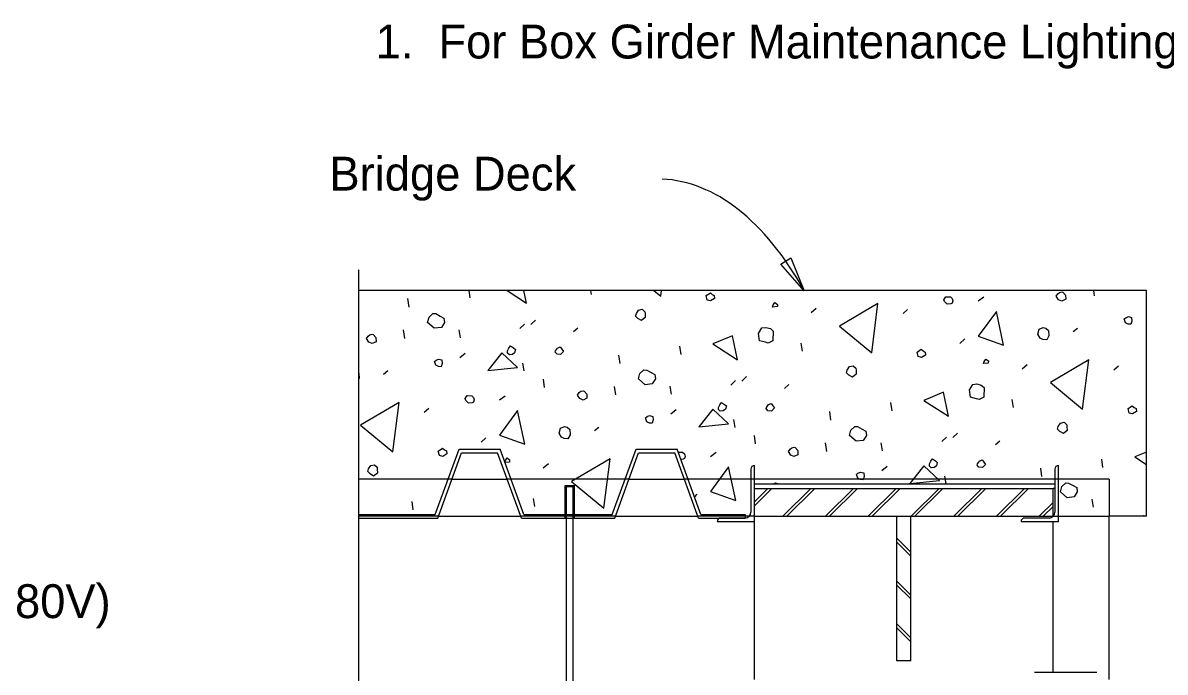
# Model space of a CAD drawing. Extents: x 112544 to 112597.1, y 111084 to 111107.1.
# Drawn here: x 112565.15 to 112570.25, y 111092.74 to 111095.64 of the extents above; entities that cross this region are included whole.
import ezdxf

# ---------------------------------------------------------------- set-up
doc = ezdxf.new("R2010")
doc.units = 0
for name, color, linetype in [('Dimension', 7, 'Continuous'), ('Lighting', 7, 'Continuous'), ('Miscellaneous', 7, 'Continuous'), ('SteelGirder', 7, 'Continuous'), ('SteelGirder_h', 7, 'Continuous'), ('SupstrConc', 7, 'Continuous'), ('TextStructures', 7, 'Continuous')]:
    doc.layers.add(name, color=color, linetype=linetype)

msp = doc.modelspace()

# ---------------------------------------------------------------- linework, layer by layer
at = {"layer": 'Dimension'}
msp.add_lwpolyline([(112568.635, 111094.4391), (112568.5303, 111094.558), (112568.5754, 111094.5859)], close=True, dxfattribs=at)
msp.add_lwpolyline([(112566.6473, 111092.2662), (112566.6473, 111094.5328)], dxfattribs=at)
msp.add_ellipse((112567.8899, 111092.5703), major_axis=(-0.1111, -2.3674), ratio=0.464296, start_param=2.502126, end_param=3.141581, dxfattribs=at)
at = {"layer": 'Lighting'}
msp.add_line((112569.6635, 111092.7352), (112569.9409, 111092.7352), dxfattribs=at)
at = {"layer": 'Miscellaneous'}
for p, q in [((112567.1434, 111094.4066), (112567.1387, 111094.4392)), ((112567.6858, 111094.4217), (112567.6828, 111094.4392)), ((112569.9307, 111094.4155), (112569.9273, 111094.4392)), ((112566.8711, 111094.3657), (112566.8656, 111094.4034)), ((112569.4376, 111094.4104), (112569.4118, 111094.3915)), ((112568.689, 111094.36), (112568.6657, 111094.3403)), ((112569.0965, 111094.3543), (112569.0761, 111094.3365)), ((112567.101, 111094.229), (112567.095, 111094.2643)), ((112567.3865, 111094.2897), (112567.3655, 111094.2694)), ((112567.4353, 111094.3077), (112567.4143, 111094.2874)), ((112567.6251, 111094.2723), (112567.6048, 111094.2545)), ((112569.8555, 111094.27), (112569.8358, 111094.2546)), ((112566.8517, 111094.2259), (112566.8463, 111094.2636)), ((112569.3514, 111094.2239), (112569.3304, 111094.2036)), ((112568.0852, 111094.1542), (112568.0798, 111094.1919)), ((112568.6276, 111094.1694), (112568.6215, 111094.2046)), ((112567.1211, 111094.1589), (112567.0977, 111094.1393)), ((112567.3848, 111094.0805), (112567.3787, 111094.1158)), ((112567.8128, 111094.1133), (112567.8074, 111094.151)), ((112566.7765, 111094.0804), (112566.7569, 111094.065)), ((112569.6308, 111094.1076), (112569.6074, 111094.088)), ((112570.0382, 111094.102), (112570.0179, 111094.0841)), ((112567.4763, 111094.0068), (112567.4709, 111094.0445)), ((112567.7935, 111093.9736), (112567.7881, 111094.0113)), ((112568.0428, 111093.9767), (112568.0367, 111094.0119)), ((112568.3282, 111094.0373), (112568.3073, 111094.0171)), ((112568.3771, 111094.0553), (112568.3561, 111094.0351)), ((112568.5669, 111094.02), (112568.5466, 111094.0021)), ((112567.3004, 111093.9685), (112567.2746, 111093.9496)), ((112566.9593, 111093.9124), (112566.9389, 111093.8946)), ((112569.027, 111093.9019), (112569.0216, 111093.9396)), ((112569.5694, 111093.917), (112569.5633, 111093.9523)), ((112568.0629, 111093.9066), (112568.0395, 111093.887)), ((112568.3265, 111093.8282), (112568.3205, 111093.8634)), ((112568.7546, 111093.861), (112568.7492, 111093.8987)), ((112567.7183, 111093.8281), (112567.6986, 111093.8126)), ((112567.2142, 111093.782), (112567.1932, 111093.7617)), ((112568.4181, 111093.7545), (112568.4127, 111093.7921)), ((112568.7353, 111093.7212), (112568.7299, 111093.7589)), ((112568.9846, 111093.7243), (112568.9785, 111093.7596)), ((112569.27, 111093.785), (112569.2491, 111093.7647)), ((112569.3188, 111093.803), (112569.2979, 111093.7827)), ((112569.5087, 111093.7676), (112569.4883, 111093.7498)), ((112566.9878, 111093.4392), (112567.094, 111093.7309)), ((112566.9987, 111093.4236), (112567.1049, 111093.7153)), ((112567.094, 111093.7309), (112567.2773, 111093.7309)), ((112567.1049, 111093.7153), (112567.2664, 111093.7153)), ((112567.3726, 111093.4236), (112567.2664, 111093.7153)), ((112567.3835, 111093.4392), (112567.2773, 111093.7309)), ((112567.7782, 111093.4392), (112567.8844, 111093.7309)), ((112567.7892, 111093.4236), (112567.8953, 111093.7153)), ((112567.8844, 111093.7309), (112568.0677, 111093.7309)), ((112567.8953, 111093.7153), (112568.0568, 111093.7153)), ((112568.163, 111093.4236), (112568.0568, 111093.7153)), ((112568.1739, 111093.4392), (112568.0677, 111093.7309)), ((112568.2422, 111093.7162), (112568.2164, 111093.6972)), ((112567.4936, 111093.6657), (112567.4702, 111093.6461)), ((112568.413, 111093.408), (112568.4129, 111093.658)), ((112569.0046, 111093.6542), (112568.9813, 111093.6346)), ((112569.7697, 111093.4079), (112569.7697, 111093.6579)), ((112569.9688, 111093.6495), (112569.9633, 111093.6872)), ((112568.3973, 111093.6423), (112568.3973, 111093.4496)), ((112569.2681, 111093.577), (112569.2622, 111093.6111)), ((112569.6964, 111093.6086), (112569.691, 111093.6463)), ((112569.754, 111093.6423), (112569.7541, 111093.4496)), ((112568.413, 111093.577), (112569.754, 111093.577)), ((112568.413, 111093.496), (112568.4731, 111093.5562)), ((112568.413, 111093.4783), (112568.4908, 111093.5562)), ((112568.5391, 111093.4312), (112568.6641, 111093.5562)), ((112568.5567, 111093.4312), (112568.6817, 111093.5562)), ((112568.73, 111093.4312), (112568.855, 111093.5562)), ((112568.7477, 111093.4312), (112568.8727, 111093.5562)), ((112568.9209, 111093.4312), (112569.0459, 111093.5562)), ((112568.9386, 111093.4312), (112569.0636, 111093.5562)), ((112569.1118, 111093.4312), (112569.2368, 111093.5562)), ((112569.1295, 111093.4312), (112569.2545, 111093.5562)), ((112569.3027, 111093.4312), (112569.4277, 111093.5562)), ((112569.3204, 111093.4312), (112569.4454, 111093.5562)), ((112569.4937, 111093.4312), (112569.6187, 111093.5562)), ((112569.5113, 111093.4312), (112569.6363, 111093.5562)), ((112569.754, 111093.5562), (112569.7464, 111093.5562)), ((112567.4322, 111093.4751), (112567.4261, 111093.5104)), ((112568.156, 111093.5296), (112568.1449, 111093.5189)), ((112569.9264, 111093.472), (112569.9203, 111093.5072)), ((112566.8898, 111093.46), (112566.8844, 111093.4977)), ((112569.6846, 111093.4312), (112569.7464, 111093.493)), ((112569.7023, 111093.4312), (112569.7464, 111093.4753)), ((112566.6473, 111093.4392), (112566.9878, 111093.4392)), ((112566.6473, 111093.4236), (112566.9987, 111093.4236)), ((112567.3726, 111093.4236), (112567.7892, 111093.4236)), ((112567.3835, 111093.4392), (112567.7782, 111093.4392)), ((112568.163, 111093.4236), (112568.3713, 111093.4236)), ((112568.1739, 111093.4392), (112568.3713, 111093.4392)), ((112568.2463, 111093.4079), (112568.413, 111093.408)), ((112568.3713, 111093.4236), (112568.2619, 111093.4236)), ((112568.3713, 111093.4392), (112568.3713, 111093.4236)), ((112569.603, 111093.4079), (112569.7697, 111093.4079)), ((112569.728, 111093.4235), (112569.6186, 111093.4235)), ((112569.1109, 111093.2706), (112569.0485, 111093.333)), ((112569.1109, 111093.253), (112569.0485, 111093.3154)), ((112569.1109, 111093.0797), (112569.0485, 111093.1421)), ((112569.1109, 111093.062), (112569.0485, 111093.1244)), ((112569.1109, 111092.8888), (112569.0485, 111092.9512)), ((112569.1109, 111092.8711), (112569.0485, 111092.9335))]:
    msp.add_line(p, q, dxfattribs=at)
for points in [[(112567.3084, 111094.4392), (112567.3959, 111094.3829)], [(112567.3959, 111094.3829), (112567.3838, 111094.4392)], [(112567.9639, 111094.4392), (112567.9944, 111094.4141)], [(112567.9944, 111094.4141), (112567.9976, 111094.4392)], [(112568.235, 111094.404), (112568.2166, 111094.3934), (112568.2021, 111094.3973), (112568.197, 111094.4168), (112568.216, 111094.4298), (112568.2243, 111094.4224), (112568.2334, 111094.4174), (112568.235, 111094.404), (112568.2362, 111094.4088)], [(112569.8022, 111094.4189), (112569.8025, 111094.4007), (112569.7848, 111094.3925), (112569.7709, 111094.3988), (112569.7597, 111094.4147), (112569.7678, 111094.4255), (112569.7745, 111094.4315), (112569.7855, 111094.4337), (112569.7903, 111094.4324), (112569.8022, 111094.4189)], [(112568.5151, 111094.3677), (112568.4939, 111094.3657), (112568.4964, 111094.3753), (112568.5045, 111094.3861), (112568.5153, 111094.378), (112568.5151, 111094.3677)], [(112568.9362, 111094.1617), (112568.9641, 111094.382), (112568.792, 111094.2806), (112568.9362, 111094.1617)], [(112569.2959, 111094.3837), (112569.2897, 111094.3802), (112569.2739, 111094.3792), (112569.2614, 111094.3904), (112569.2585, 111094.3989), (112569.2672, 111094.4121), (112569.2878, 111094.4117), (112569.2962, 111094.4043), (112569.2984, 111094.3934), (112569.2959, 111094.3837)], [(112567.0288, 111094.2975), (112567.0151, 111094.2753), (112566.9829, 111094.271), (112566.9536, 111094.297), (112566.9601, 111094.3211), (112566.9773, 111094.3372), (112566.99, 111094.3364), (112567.0105, 111094.3257), (112567.0261, 111094.3164), (112567.0288, 111094.2975)], [(112567.9246, 111094.337), (112567.9249, 111094.3188), (112567.9082, 111094.3052), (112567.8926, 111094.3145), (112567.8825, 111094.325), (112567.8857, 111094.3371), (112567.8951, 111094.3527), (112567.9115, 111094.3561), (112567.9241, 111094.3449), (112567.9246, 111094.337)], [(112569.525, 111094.1955), (112569.4929, 111094.3464), (112569.4116, 111094.2362), (112569.525, 111094.1955)], [(112570.0974, 111094.3035), (112570.0935, 111094.289), (112570.0808, 111094.2899), (112570.0694, 111094.2955), (112570.0636, 111094.3126), (112570.0704, 111094.3185), (112570.082, 111094.3232), (112570.0965, 111094.3193), (112570.0974, 111094.3035)], [(112568.4963, 111094.2589), (112568.495, 111094.2153), (112568.4742, 111094.2053), (112568.4621, 111094.2085), (112568.4355, 111094.2157), (112568.4312, 111094.2479), (112568.4456, 111094.2725), (112568.4644, 111094.2752), (112568.4838, 111094.27), (112568.4963, 111094.2589)], [(112569.7262, 111094.2606), (112569.7276, 111094.237), (112569.7176, 111094.2189), (112569.7, 111094.2211), (112569.6886, 111094.2267), (112569.678, 111094.2451), (112569.6838, 111094.2668), (112569.7015, 111094.275), (112569.7136, 111094.2718), (112569.7262, 111094.2606)], [(112566.7232, 111094.2293), (112566.7235, 111094.2111), (112566.7058, 111094.2029), (112566.692, 111094.2092), (112566.6807, 111094.2252), (112566.6888, 111094.2359), (112566.6955, 111094.2419), (112566.7065, 111094.2441), (112566.7113, 111094.2428), (112566.7232, 111094.2293)], [(112568.3377, 111094.1306), (112568.3146, 111094.2377), (112568.2273, 111094.2016), (112568.3377, 111094.1306)], [(112567.3419, 111094.1619), (112567.332, 111094.1542), (112567.3187, 111094.1526), (112567.3103, 111094.16), (112567.3105, 111094.1703), (112567.3161, 111094.1817), (112567.3242, 111094.1925), (112567.3374, 111094.1838), (112567.3457, 111094.1764), (112567.3419, 111094.1619)], [(112567.5609, 111094.1679), (112567.5467, 111094.1536), (112567.5316, 111094.1551), (112567.5238, 111094.1649), (112567.5251, 111094.1697), (112567.5338, 111094.1829), (112567.5454, 111094.1876), (112567.5532, 111094.1777), (112567.5609, 111094.1679)], [(112569.1767, 111094.1516), (112569.1584, 111094.141), (112569.1439, 111094.1449), (112569.1387, 111094.1644), (112569.1578, 111094.1774), (112569.1661, 111094.17), (112569.1751, 111094.165), (112569.1767, 111094.1516), (112569.178, 111094.1565)], [(112567.0184, 111094.114), (112567.0146, 111094.0995), (112567.0018, 111094.1003), (112566.9904, 111094.1059), (112566.9846, 111094.123), (112566.9914, 111094.129), (112567.003, 111094.1336), (112567.0175, 111094.1297), (112567.0184, 111094.114)], [(112567.3553, 111094.0962), (112567.2849, 111094.1616), (112567.2223, 111094.0826), (112567.3553, 111094.0962)], [(112569.4569, 111094.1154), (112569.4356, 111094.1133), (112569.4382, 111094.123), (112569.4463, 111094.1338), (112569.4571, 111094.1257), (112569.4569, 111094.1154)], [(112569.8779, 111093.9094), (112569.9059, 111094.1297), (112569.7338, 111094.0283), (112569.8779, 111093.9094)], [(112566.6473, 111094.07), (112566.6486, 111094.0474), (112566.6473, 111094.045)], [(112567.9706, 111094.0452), (112567.9569, 111094.023), (112567.9247, 111094.0187), (112567.8954, 111094.0446), (112567.9018, 111094.0688), (112567.9191, 111094.0849), (112567.9318, 111094.084), (112567.9523, 111094.0734), (112567.9679, 111094.064), (112567.9706, 111094.0452)], [(112568.8663, 111094.0847), (112568.8666, 111094.0665), (112568.85, 111094.0528), (112568.8344, 111094.0622), (112568.8243, 111094.0727), (112568.8275, 111094.0847), (112568.8369, 111094.1003), (112568.8533, 111094.1037), (112568.8659, 111094.0926), (112568.8663, 111094.0847)], [(112569.4381, 111094.0065), (112569.4367, 111093.9629), (112569.416, 111093.9529), (112569.4039, 111093.9562), (112569.3773, 111093.9633), (112569.373, 111093.9955), (112569.3874, 111094.0201), (112569.4062, 111094.0229), (112569.4255, 111094.0177), (112569.4381, 111094.0065)], [(112567.1587, 111093.9418), (112567.1525, 111093.9383), (112567.1368, 111093.9373), (112567.1242, 111093.9484), (112567.1213, 111093.957), (112567.13, 111093.9702), (112567.1506, 111093.9698), (112567.159, 111093.9624), (112567.1612, 111093.9515), (112567.1587, 111093.9418)], [(112567.665, 111093.9769), (112567.6653, 111093.9587), (112567.6476, 111093.9506), (112567.6337, 111093.9569), (112567.6225, 111093.9728), (112567.6306, 111093.9836), (112567.6373, 111093.9895), (112567.6483, 111093.9918), (112567.6531, 111093.9905), (112567.665, 111093.9769)], [(112569.2795, 111093.8782), (112569.2564, 111093.9853), (112569.1691, 111093.9492), (112569.2795, 111093.8782)], [(112566.799, 111093.7198), (112566.8269, 111093.9401), (112566.6548, 111093.8387), (112566.799, 111093.7198)], [(112568.2971, 111093.8438), (112568.2266, 111093.9093), (112568.1641, 111093.8303), (112568.2971, 111093.8438)], [(112568.2836, 111093.9095), (112568.2738, 111093.9018), (112568.2604, 111093.9002), (112568.2521, 111093.9076), (112568.2522, 111093.9179), (112568.2579, 111093.9294), (112568.266, 111093.9402), (112568.2792, 111093.9314), (112568.2875, 111093.924), (112568.2836, 111093.9095)], [(112568.5027, 111093.9156), (112568.4885, 111093.9012), (112568.4733, 111093.9027), (112568.4656, 111093.9125), (112568.4669, 111093.9174), (112568.4756, 111093.9306), (112568.4872, 111093.9352), (112568.4949, 111093.9254), (112568.5027, 111093.9156)], [(112570.1185, 111093.8993), (112570.1001, 111093.8887), (112570.0856, 111093.8926), (112570.0805, 111093.9121), (112570.0995, 111093.9251), (112570.1079, 111093.9177), (112570.1169, 111093.9127), (112570.1185, 111093.8993), (112570.1198, 111093.9041)], [(112567.3878, 111093.7536), (112567.3557, 111093.9045), (112567.2744, 111093.7943), (112567.3878, 111093.7536)], [(112567.9602, 111093.8616), (112567.9563, 111093.8471), (112567.9436, 111093.8479), (112567.9322, 111093.8536), (112567.9264, 111093.8707), (112567.9332, 111093.8766), (112567.9448, 111093.8813), (112567.9593, 111093.8774), (112567.9602, 111093.8616)], [(112567.589, 111093.8187), (112567.5904, 111093.7951), (112567.5804, 111093.777), (112567.5628, 111093.7792), (112567.5514, 111093.7848), (112567.5408, 111093.8032), (112567.5466, 111093.8249), (112567.5643, 111093.8331), (112567.5764, 111093.8299), (112567.589, 111093.8187)], [(112568.9124, 111093.7928), (112568.8986, 111093.7706), (112568.8664, 111093.7663), (112568.8372, 111093.7923), (112568.8436, 111093.8164), (112568.8609, 111093.8325), (112568.8736, 111093.8317), (112568.894, 111093.821), (112568.9096, 111093.8117), (112568.9124, 111093.7928)], [(112569.8081, 111093.8323), (112569.8084, 111093.8141), (112569.7918, 111093.8005), (112569.7762, 111093.8098), (112569.7661, 111093.8203), (112569.7693, 111093.8324), (112569.7787, 111093.848), (112569.7951, 111093.8514), (112569.8076, 111093.8402), (112569.8081, 111093.8323)], [(112567.0395, 111093.7097), (112567.0212, 111093.6991), (112567.0067, 111093.703), (112567.0015, 111093.7225), (112567.0206, 111093.7355), (112567.0289, 111093.7281), (112567.0379, 111093.7231), (112567.0395, 111093.7097), (112567.0408, 111093.7146)], [(112568.0725, 111093.7178), (112568.0924, 111093.7175), (112568.1008, 111093.7101), (112568.103, 111093.6991), (112568.1004, 111093.6895)], [(112568.6068, 111093.7246), (112568.6071, 111093.7064), (112568.5894, 111093.6982), (112568.5755, 111093.7045), (112568.5643, 111093.7205), (112568.5723, 111093.7312), (112568.5791, 111093.7372), (112568.5901, 111093.7394), (112568.5949, 111093.7381), (112568.6068, 111093.7246)], [(112570.163, 111093.7184), (112570.1109, 111093.6969), (112570.163, 111093.6633)], [(112566.7291, 111093.6428), (112566.7294, 111093.6246), (112566.7128, 111093.6109), (112566.6972, 111093.6203), (112566.6871, 111093.6308), (112566.6903, 111093.6428), (112566.6997, 111093.6584), (112566.7161, 111093.6618), (112566.7287, 111093.6507), (112566.7291, 111093.6428)], [(112567.2987, 111093.6722), (112567.301, 111093.6811), (112567.3091, 111093.6919), (112567.3199, 111093.6838), (112567.3197, 111093.6735)], [(112567.3197, 111093.6735), (112567.2989, 111093.6715)], [(112567.7407, 111093.4675), (112567.7687, 111093.6878), (112567.5966, 111093.5863), (112567.7407, 111093.4675)], [(112568.1004, 111093.6895), (112568.0943, 111093.6859), (112568.0843, 111093.6853)], [(112568.3295, 111093.5012), (112568.2975, 111093.6522), (112568.2162, 111093.542), (112568.3295, 111093.5012)], [(112569.2389, 111093.5915), (112569.1684, 111093.6569), (112569.1058, 111093.5779), (112569.2389, 111093.5915)], [(112569.2254, 111093.6572), (112569.2156, 111093.6495), (112569.2022, 111093.6479), (112569.1939, 111093.6553), (112569.194, 111093.6656), (112569.1997, 111093.677), (112569.2077, 111093.6878), (112569.2209, 111093.6791), (112569.2293, 111093.6717), (112569.2254, 111093.6572)], [(112569.4444, 111093.6632), (112569.4302, 111093.6489), (112569.4151, 111093.6504), (112569.4074, 111093.6602), (112569.4087, 111093.665), (112569.4174, 111093.6782), (112569.429, 111093.6829), (112569.4367, 111093.673), (112569.4444, 111093.6632)], [(112568.902, 111093.6093), (112568.8981, 111093.5948), (112568.8854, 111093.5956), (112568.874, 111093.6012), (112568.8682, 111093.6183), (112568.875, 111093.6243), (112568.8866, 111093.6289), (112568.901, 111093.625), (112568.902, 111093.6093)], [(112568.4979, 111093.577), (112568.5061, 111093.5807), (112568.5182, 111093.5775), (112568.5188, 111093.577)], [(112569.8541, 111093.5405), (112569.8404, 111093.5183), (112569.8082, 111093.514), (112569.7789, 111093.5399), (112569.7854, 111093.5641), (112569.8027, 111093.5802), (112569.8154, 111093.5793), (112569.8358, 111093.5687), (112569.8514, 111093.5593), (112569.8541, 111093.5405)], [(112568.2506, 111093.4392), (112568.2509, 111093.4395), (112568.2513, 111093.4392)], [(112570.1463, 111093.4312), (112570.1495, 111093.4355), (112570.156, 111093.4312)]]:
    msp.add_lwpolyline(points, dxfattribs=at)
for centre, radius, start, end in [((112568.4129, 111093.6423), 0.0156, 90.0047, 180.0047), ((112569.7697, 111093.6423), 0.0156, 90.0047, 180.0047), ((112568.3713, 111093.4496), 0.026, 270.0047, 0.0047), ((112569.728, 111093.4496), 0.026, 270.0047, 0.0047), ((112568.2619, 111093.4079), 0.0156, 90.0047, 180.0047), ((112569.6186, 111093.4079), 0.0156, 90.0047, 180.0047)]:
    msp.add_arc(centre, radius, start, end, dxfattribs=at)
at = {"layer": 'SteelGirder'}
for p, q in [((112567.0622, 111093.5979), (112567.3091, 111093.5979)), ((112567.5679, 111093.5694), (112567.6095, 111093.5694)), ((112567.5679, 111093.4236), (112567.5679, 111093.5694)), ((112567.5731, 111092.5039), (112567.5731, 111093.5642)), ((112567.5731, 111093.5642), (112567.6043, 111093.5642)), ((112567.6043, 111092.5039), (112567.6043, 111093.5642)), ((112567.6095, 111093.4236), (112567.6095, 111093.5694)), ((112567.8526, 111093.5979), (112568.0995, 111093.5979)), ((112568.413, 111093.5562), (112569.7464, 111093.5562)), ((112568.413, 111093.408), (112568.413, 111093.5562)), ((112569.7464, 111093.4312), (112569.7464, 111093.5562)), ((112567.0015, 111093.4312), (112567.3698, 111093.4312)), ((112567.7919, 111093.4312), (112568.1602, 111093.4312)), ((112568.413, 111093.4312), (112569.9964, 111093.4312)), ((112568.413, 111092.7018), (112568.413, 111093.408)), ((112569.0485, 111092.7851), (112569.0485, 111093.4312)), ((112569.1109, 111092.7851), (112569.1109, 111093.4312)), ((112569.7464, 111092.7352), (112569.7464, 111093.4079)), ((112569.9964, 111092.7019), (112569.9964, 111093.4312)), ((112569.1109, 111092.7851), (112569.0485, 111092.7851))]:
    msp.add_line(p, q, dxfattribs=at)
at = {"layer": 'SteelGirder_h'}
for p, q in [((112567.0622, 111093.5979), (112566.6473, 111093.5979)), ((112567.8526, 111093.5979), (112567.3091, 111093.5979)), ((112569.9964, 111093.5979), (112568.0995, 111093.5979)), ((112569.9964, 111093.5979), (112569.9964, 111093.4312)), ((112567.0015, 111093.4312), (112566.6473, 111093.4312)), ((112567.7919, 111093.4312), (112567.3698, 111093.4312)), ((112568.413, 111093.4312), (112568.1602, 111093.4312))]:
    msp.add_line(p, q, dxfattribs=at)
at = {"layer": 'SupstrConc'}
for p, q in [((112570.163, 111094.4392), (112566.6473, 111094.4392)), ((112570.163, 111093.4312), (112570.163, 111094.4392)), ((112570.163, 111093.4312), (112569.9964, 111093.4312))]:
    msp.add_line(p, q, dxfattribs=at)

# ---------------------------------------------------------------- texts
at = {"layer": 'Dimension'}
msp.add_text('1.  For Box Girder Maintenance Lighting Notes see Sheet 1.', height=0.1512, dxfattribs=at).set_placement((112566.7213, 111095.4761))
at = {"layer": 'TextStructures'}
for s, p in [('Bridge Deck', (112566.5155, 111094.8861)), ('Conduit (480V)', (112564.179, 111092.9766))]:
    msp.add_text(s, height=0.1512, dxfattribs=at).set_placement(p)

doc.saveas('drawing.dxf')
